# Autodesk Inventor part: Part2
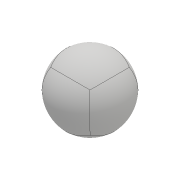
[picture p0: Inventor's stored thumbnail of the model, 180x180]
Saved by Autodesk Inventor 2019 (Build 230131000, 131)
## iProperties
Created: 2015-07
Part Number: Part2
Material: Generic
Document SubType Name: Modeling
Designer: Sandeep
Density: 1 g/cm^3
Appearance: Default
Author: Sandeep
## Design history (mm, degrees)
feature "Form1"
body "Solid1"
